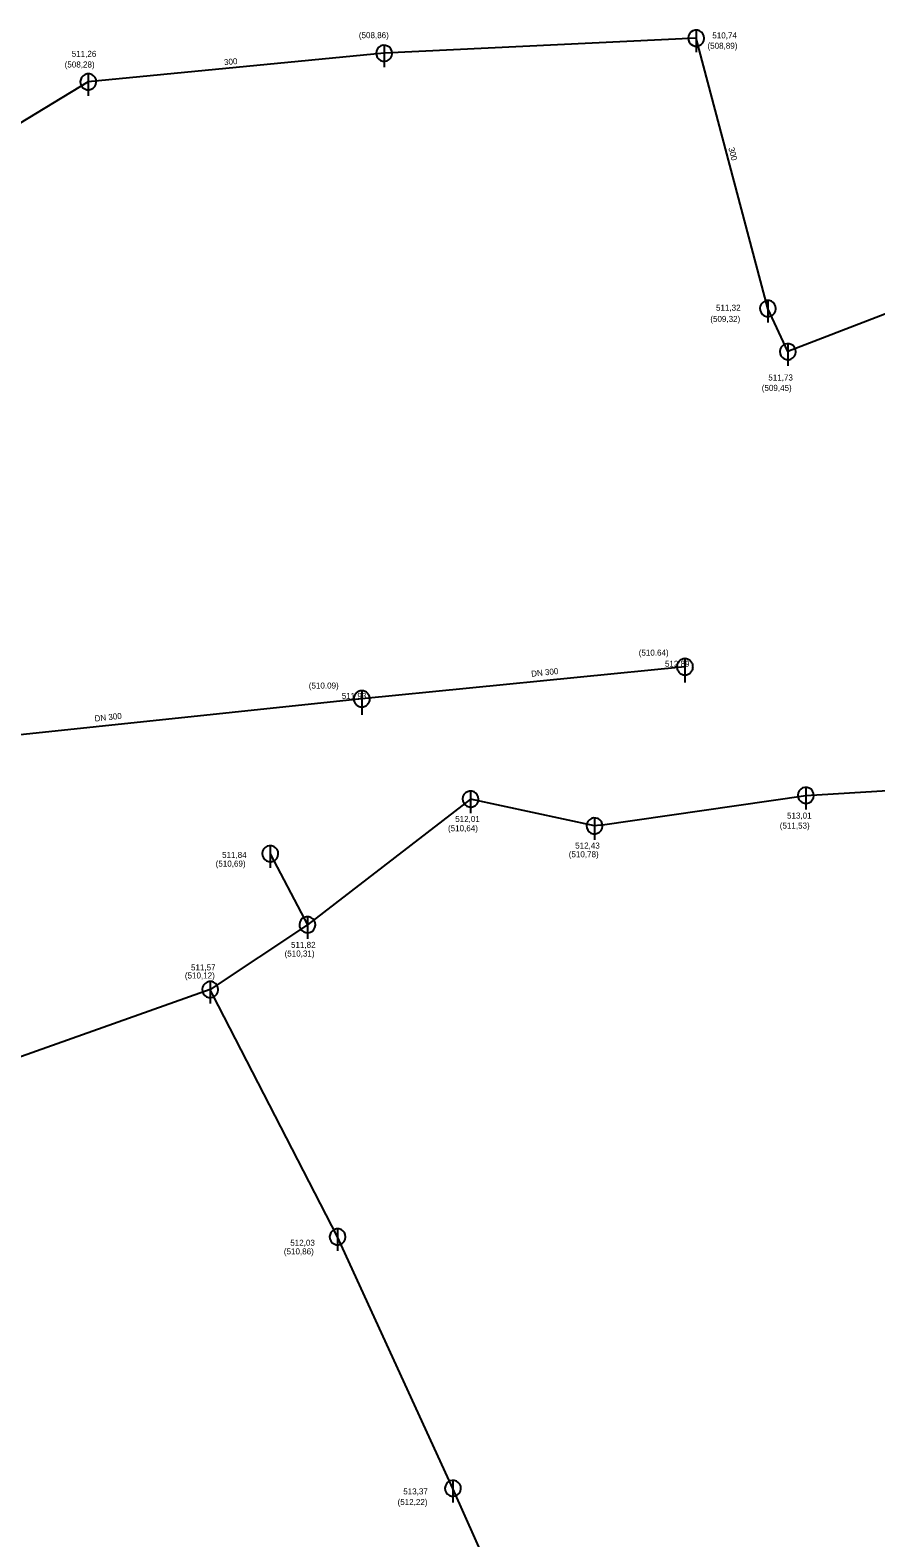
# Model space of a CAD drawing. Extents: x -476058 to -471893, y -1155786 to -1152000.
# Drawn here: x -474932.1 to -474826.6, y -1154263.3 to -1154075.2 of the extents above; entities that cross this region are included whole.
import ezdxf

# ---------------------------------------------------------------- set-up
doc = ezdxf.new("R2010")
doc.units = 0
for name, color, linetype in [('Vrstva 1', 7, 'Continuous'), ('Vrstva 10', 7, 'Continuous'), ('Vrstva 16', 7, 'Continuous'), ('Vrstva 18', 7, 'Continuous'), ('Vrstva 3', 7, 'Continuous'), ('Vrstva 35', 7, 'Continuous'), ('Vrstva 4', 7, 'Continuous'), ('Vrstva 45', 7, 'Continuous'), ('Vrstva 50', 7, 'Continuous')]:
    doc.layers.add(name, color=color, linetype=linetype)

msp = doc.modelspace()

# ---------------------------------------------------------------- linework, layer by layer
at = {"layer": 'Vrstva 1'}
for p, q in [((-474850.38, -1154154.67), (-474850.38, -1154154.67)), ((-474890.71, -1154158.68), (-474890.71, -1154158.68))]:
    msp.add_line(p, q, dxfattribs=at)
at = {"layer": 'Vrstva 10'}
for p, q in [((-474848.98, -1154075.25), (-474848.98, -1154078)), ((-474887.92, -1154077.14), (-474887.92, -1154079.88)), ((-474924.83, -1154080.7), (-474924.83, -1154083.44)), ((-474840.03, -1154108.98), (-474840.03, -1154111.73)), ((-474837.54, -1154114.36), (-474837.54, -1154117.11)), ((-474835.3, -1154169.71), (-474835.3, -1154172.46)), ((-474877.13, -1154170.17), (-474877.13, -1154172.92)), ((-474861.66, -1154173.53), (-474861.66, -1154176.27)), ((-474902.12, -1154176.99), (-474902.12, -1154179.74)), ((-474897.49, -1154185.85), (-474897.49, -1154188.6)), ((-474909.62, -1154193.94), (-474909.62, -1154196.69)), ((-474893.72, -1154224.79), (-474893.72, -1154227.54)), ((-474879.33, -1154256.17), (-474879.33, -1154258.92))]:
    msp.add_line(p, q, dxfattribs=at)
for points in [[(-474847.98, -1154076.25), (-474848.02, -1154075.97), (-474848.14, -1154075.71), (-474848.32, -1154075.5), (-474848.55, -1154075.34), (-474848.83, -1154075.26), (-474849.11, -1154075.26), (-474849.38, -1154075.33), (-474849.62, -1154075.48), (-474849.81, -1154075.69), (-474849.93, -1154075.94), (-474849.98, -1154076.22), (-474849.95, -1154076.5), (-474849.84, -1154076.76), (-474849.66, -1154076.98), (-474849.43, -1154077.14), (-474849.16, -1154077.23), (-474848.88, -1154077.25), (-474848.61, -1154077.18), (-474848.36, -1154077.04), (-474848.17, -1154076.83), (-474848.04, -1154076.58), (-474847.98, -1154076.31), (-474847.98, -1154076.25)], [(-474886.92, -1154078.14), (-474886.96, -1154077.86), (-474887.07, -1154077.6), (-474887.26, -1154077.39), (-474887.49, -1154077.23), (-474887.76, -1154077.15), (-474888.04, -1154077.14), (-474888.32, -1154077.22), (-474888.56, -1154077.37), (-474888.75, -1154077.58), (-474888.87, -1154077.83), (-474888.92, -1154078.11), (-474888.89, -1154078.39), (-474888.78, -1154078.65), (-474888.6, -1154078.87), (-474888.37, -1154079.03), (-474888.1, -1154079.12), (-474887.82, -1154079.13), (-474887.54, -1154079.06), (-474887.3, -1154078.92), (-474887.1, -1154078.72), (-474886.97, -1154078.47), (-474886.92, -1154078.19), (-474886.92, -1154078.14)], [(-474923.83, -1154081.7), (-474923.87, -1154081.42), (-474923.99, -1154081.16), (-474924.17, -1154080.94), (-474924.41, -1154080.79), (-474924.67, -1154080.71), (-474924.96, -1154080.7), (-474925.23, -1154080.78), (-474925.47, -1154080.93), (-474925.66, -1154081.14), (-474925.78, -1154081.39), (-474925.83, -1154081.67), (-474925.8, -1154081.95), (-474925.69, -1154082.21), (-474925.51, -1154082.43), (-474925.28, -1154082.59), (-474925.01, -1154082.68), (-474924.73, -1154082.69), (-474924.46, -1154082.62), (-474924.21, -1154082.48), (-474924.02, -1154082.28), (-474923.89, -1154082.03), (-474923.83, -1154081.75), (-474923.83, -1154081.7)], [(-474839.03, -1154109.98), (-474839.07, -1154109.7), (-474839.19, -1154109.44), (-474839.37, -1154109.23), (-474839.6, -1154109.07), (-474839.88, -1154108.99), (-474840.16, -1154108.99), (-474840.43, -1154109.06), (-474840.67, -1154109.21), (-474840.86, -1154109.42), (-474840.98, -1154109.67), (-474841.03, -1154109.95), (-474841, -1154110.23), (-474840.89, -1154110.49), (-474840.71, -1154110.71), (-474840.48, -1154110.87), (-474840.21, -1154110.96), (-474839.93, -1154110.98), (-474839.66, -1154110.91), (-474839.41, -1154110.77), (-474839.22, -1154110.56), (-474839.09, -1154110.31), (-474839.03, -1154110.04), (-474839.03, -1154109.98)], [(-474836.54, -1154115.36), (-474836.58, -1154115.08), (-474836.7, -1154114.82), (-474836.88, -1154114.61), (-474837.11, -1154114.46), (-474837.39, -1154114.37), (-474837.67, -1154114.37), (-474837.94, -1154114.44), (-474838.18, -1154114.59), (-474838.37, -1154114.8), (-474838.49, -1154115.05), (-474838.54, -1154115.33), (-474838.51, -1154115.61), (-474838.4, -1154115.87), (-474838.22, -1154116.09), (-474837.99, -1154116.25), (-474837.72, -1154116.34), (-474837.44, -1154116.36), (-474837.17, -1154116.29), (-474836.92, -1154116.15), (-474836.73, -1154115.94), (-474836.6, -1154115.69), (-474836.54, -1154115.42), (-474836.54, -1154115.36)], [(-474849.37, -1154154.67), (-474849.38, -1154154.56), (-474849.39, -1154154.46), (-474849.42, -1154154.36), (-474849.46, -1154154.26), (-474849.51, -1154154.17), (-474849.57, -1154154.08), (-474849.63, -1154154), (-474849.71, -1154153.92), (-474849.79, -1154153.85), (-474849.88, -1154153.8), (-474849.97, -1154153.75), (-474850.07, -1154153.71), (-474850.17, -1154153.68), (-474850.28, -1154153.67), (-474850.38, -1154153.66), (-474850.48, -1154153.67), (-474850.59, -1154153.68), (-474850.69, -1154153.71), (-474850.79, -1154153.75), (-474850.88, -1154153.8), (-474850.97, -1154153.85), (-474851.05, -1154153.92), (-474851.13, -1154154), (-474851.2, -1154154.08), (-474851.25, -1154154.17), (-474851.3, -1154154.26), (-474851.34, -1154154.36), (-474851.37, -1154154.46), (-474851.38, -1154154.56), (-474851.39, -1154154.67), (-474851.38, -1154154.78), (-474851.37, -1154154.88), (-474851.34, -1154154.98), (-474851.3, -1154155.08), (-474851.25, -1154155.17), (-474851.2, -1154155.26), (-474851.13, -1154155.34), (-474851.05, -1154155.42), (-474850.97, -1154155.49), (-474850.88, -1154155.54), (-474850.79, -1154155.59), (-474850.69, -1154155.63), (-474850.59, -1154155.66), (-474850.48, -1154155.67), (-474850.38, -1154155.68), (-474850.28, -1154155.67), (-474850.17, -1154155.66), (-474850.07, -1154155.63), (-474849.97, -1154155.59), (-474849.88, -1154155.54), (-474849.79, -1154155.49), (-474849.71, -1154155.42), (-474849.63, -1154155.34), (-474849.57, -1154155.26), (-474849.51, -1154155.17), (-474849.46, -1154155.08), (-474849.42, -1154154.98), (-474849.39, -1154154.88), (-474849.38, -1154154.78), (-474849.37, -1154154.67)], [(-474850.38, -1154153.66), (-474850.38, -1154156.64)], [(-474889.7, -1154158.68), (-474889.71, -1154158.57), (-474889.72, -1154158.47), (-474889.75, -1154158.37), (-474889.79, -1154158.27), (-474889.84, -1154158.18), (-474889.9, -1154158.09), (-474889.96, -1154158.01), (-474890.04, -1154157.93), (-474890.12, -1154157.86), (-474890.21, -1154157.81), (-474890.3, -1154157.76), (-474890.4, -1154157.72), (-474890.5, -1154157.69), (-474890.6, -1154157.68), (-474890.71, -1154157.67), (-474890.82, -1154157.68), (-474890.92, -1154157.69), (-474891.02, -1154157.72), (-474891.12, -1154157.76), (-474891.21, -1154157.81), (-474891.3, -1154157.86), (-474891.39, -1154157.93), (-474891.46, -1154158.01), (-474891.53, -1154158.09), (-474891.58, -1154158.18), (-474891.63, -1154158.27), (-474891.67, -1154158.37), (-474891.7, -1154158.47), (-474891.71, -1154158.57), (-474891.72, -1154158.68), (-474891.71, -1154158.78), (-474891.7, -1154158.89), (-474891.67, -1154158.99), (-474891.63, -1154159.09), (-474891.58, -1154159.18), (-474891.53, -1154159.27), (-474891.46, -1154159.35), (-474891.39, -1154159.43), (-474891.3, -1154159.5), (-474891.21, -1154159.55), (-474891.12, -1154159.6), (-474891.02, -1154159.64), (-474890.92, -1154159.67), (-474890.82, -1154159.68), (-474890.71, -1154159.69), (-474890.6, -1154159.68), (-474890.5, -1154159.67), (-474890.4, -1154159.64), (-474890.3, -1154159.6), (-474890.21, -1154159.55), (-474890.12, -1154159.5), (-474890.04, -1154159.43), (-474889.96, -1154159.35), (-474889.9, -1154159.27), (-474889.84, -1154159.18), (-474889.79, -1154159.09), (-474889.75, -1154158.99), (-474889.72, -1154158.89), (-474889.71, -1154158.78), (-474889.7, -1154158.68)], [(-474890.71, -1154157.67), (-474890.71, -1154160.65)], [(-474834.3, -1154170.71), (-474834.34, -1154170.43), (-474834.46, -1154170.17), (-474834.64, -1154169.96), (-474834.88, -1154169.8), (-474835.15, -1154169.72), (-474835.43, -1154169.72), (-474835.7, -1154169.79), (-474835.94, -1154169.94), (-474836.13, -1154170.15), (-474836.25, -1154170.4), (-474836.3, -1154170.68), (-474836.27, -1154170.96), (-474836.16, -1154171.22), (-474835.98, -1154171.44), (-474835.75, -1154171.6), (-474835.48, -1154171.69), (-474835.2, -1154171.71), (-474834.93, -1154171.64), (-474834.68, -1154171.5), (-474834.49, -1154171.29), (-474834.36, -1154171.04), (-474834.3, -1154170.77), (-474834.3, -1154170.71)], [(-474876.13, -1154171.17), (-474876.17, -1154170.89), (-474876.29, -1154170.64), (-474876.47, -1154170.42), (-474876.7, -1154170.27), (-474876.97, -1154170.18), (-474877.26, -1154170.18), (-474877.53, -1154170.26), (-474877.77, -1154170.4), (-474877.96, -1154170.61), (-474878.08, -1154170.87), (-474878.13, -1154171.14), (-474878.1, -1154171.43), (-474877.99, -1154171.69), (-474877.81, -1154171.9), (-474877.58, -1154172.07), (-474877.31, -1154172.16), (-474877.03, -1154172.17), (-474876.76, -1154172.1), (-474876.51, -1154171.96), (-474876.32, -1154171.76), (-474876.19, -1154171.51), (-474876.13, -1154171.23), (-474876.13, -1154171.17)], [(-474860.66, -1154174.53), (-474860.7, -1154174.25), (-474860.81, -1154173.99), (-474861, -1154173.78), (-474861.23, -1154173.62), (-474861.5, -1154173.54), (-474861.79, -1154173.53), (-474862.06, -1154173.61), (-474862.3, -1154173.76), (-474862.49, -1154173.97), (-474862.61, -1154174.22), (-474862.66, -1154174.5), (-474862.63, -1154174.78), (-474862.52, -1154175.04), (-474862.34, -1154175.26), (-474862.11, -1154175.42), (-474861.84, -1154175.51), (-474861.56, -1154175.52), (-474861.28, -1154175.45), (-474861.04, -1154175.31), (-474860.85, -1154175.11), (-474860.72, -1154174.86), (-474860.66, -1154174.58), (-474860.66, -1154174.53)], [(-474901.12, -1154177.99), (-474901.16, -1154177.71), (-474901.28, -1154177.46), (-474901.46, -1154177.24), (-474901.7, -1154177.09), (-474901.97, -1154177), (-474902.25, -1154177), (-474902.52, -1154177.07), (-474902.76, -1154177.22), (-474902.95, -1154177.43), (-474903.08, -1154177.69), (-474903.12, -1154177.96), (-474903.09, -1154178.25), (-474902.98, -1154178.51), (-474902.81, -1154178.72), (-474902.58, -1154178.89), (-474902.31, -1154178.98), (-474902.03, -1154178.99), (-474901.75, -1154178.92), (-474901.51, -1154178.78), (-474901.31, -1154178.57), (-474901.18, -1154178.32), (-474901.13, -1154178.05), (-474901.12, -1154177.99)], [(-474896.49, -1154186.85), (-474896.53, -1154186.57), (-474896.65, -1154186.31), (-474896.83, -1154186.1), (-474897.06, -1154185.95), (-474897.33, -1154185.86), (-474897.62, -1154185.86), (-474897.89, -1154185.93), (-474898.13, -1154186.08), (-474898.32, -1154186.29), (-474898.44, -1154186.54), (-474898.49, -1154186.82), (-474898.46, -1154187.1), (-474898.35, -1154187.36), (-474898.17, -1154187.58), (-474897.94, -1154187.75), (-474897.67, -1154187.83), (-474897.39, -1154187.85), (-474897.11, -1154187.78), (-474896.87, -1154187.64), (-474896.68, -1154187.43), (-474896.55, -1154187.18), (-474896.49, -1154186.91), (-474896.49, -1154186.85)], [(-474908.62, -1154194.94), (-474908.66, -1154194.66), (-474908.78, -1154194.4), (-474908.96, -1154194.19), (-474909.2, -1154194.03), (-474909.47, -1154193.95), (-474909.75, -1154193.95), (-474910.02, -1154194.02), (-474910.26, -1154194.17), (-474910.45, -1154194.38), (-474910.57, -1154194.63), (-474910.62, -1154194.91), (-474910.59, -1154195.19), (-474910.48, -1154195.45), (-474910.3, -1154195.67), (-474910.07, -1154195.83), (-474909.8, -1154195.92), (-474909.52, -1154195.94), (-474909.25, -1154195.87), (-474909, -1154195.73), (-474908.81, -1154195.52), (-474908.68, -1154195.27), (-474908.62, -1154195), (-474908.62, -1154194.94)], [(-474892.72, -1154225.79), (-474892.76, -1154225.51), (-474892.88, -1154225.25), (-474893.06, -1154225.04), (-474893.3, -1154224.89), (-474893.57, -1154224.8), (-474893.85, -1154224.8), (-474894.12, -1154224.87), (-474894.36, -1154225.02), (-474894.55, -1154225.23), (-474894.67, -1154225.48), (-474894.72, -1154225.76), (-474894.69, -1154226.04), (-474894.58, -1154226.3), (-474894.4, -1154226.52), (-474894.17, -1154226.68), (-474893.91, -1154226.77), (-474893.62, -1154226.79), (-474893.35, -1154226.72), (-474893.1, -1154226.58), (-474892.91, -1154226.37), (-474892.78, -1154226.12), (-474892.72, -1154225.85), (-474892.72, -1154225.79)], [(-474878.33, -1154257.17), (-474878.36, -1154256.89), (-474878.48, -1154256.63), (-474878.66, -1154256.42), (-474878.9, -1154256.26), (-474879.17, -1154256.18), (-474879.45, -1154256.18), (-474879.72, -1154256.25), (-474879.96, -1154256.4), (-474880.15, -1154256.61), (-474880.28, -1154256.86), (-474880.33, -1154257.14), (-474880.29, -1154257.42), (-474880.18, -1154257.68), (-474880.01, -1154257.9), (-474879.78, -1154258.06), (-474879.51, -1154258.15), (-474879.23, -1154258.16), (-474878.95, -1154258.09), (-474878.71, -1154257.95), (-474878.51, -1154257.75), (-474878.38, -1154257.5), (-474878.33, -1154257.22), (-474878.33, -1154257.17)]]:
    msp.add_lwpolyline(points, dxfattribs=at)
at = {"layer": 'Vrstva 35'}
msp.add_lwpolyline([(-474850.38, -1154154.67), (-474890.71, -1154158.68), (-474940.09, -1154163.87), (-474990.69, -1154169.83), (-475017.24, -1154174.14), (-475043.32, -1154186.7), (-475043.59, -1154187.73)], dxfattribs=at)
at = {"layer": 'Vrstva 45'}
for points in [[(-474848.98, -1154076.25), (-474887.92, -1154078.14)], [(-474840.03, -1154109.98), (-474848.98, -1154076.25)], [(-474887.92, -1154078.14), (-474924.83, -1154081.7)], [(-474924.83, -1154081.7), (-474969.11, -1154108.55)], [(-474780.82, -1154093.49), (-474837.54, -1154115.36)], [(-474837.54, -1154115.36), (-474840.03, -1154109.98)], [(-474877.13, -1154171.17), (-474897.49, -1154186.85)], [(-474861.66, -1154174.53), (-474877.13, -1154171.17)], [(-474897.49, -1154186.85), (-474909.62, -1154194.94)], [(-474909.62, -1154194.94), (-474938.95, -1154205.34)]]:
    msp.add_lwpolyline(points, dxfattribs=at)
at = {"layer": 'Vrstva 50'}
for points in [[(-474835.3, -1154170.71), (-474815.55, -1154169.54)], [(-474860.97, -1154174.43), (-474835.3, -1154170.71)], [(-474860.97, -1154174.43), (-474861.66, -1154174.53)], [(-474902.12, -1154177.99), (-474897.85, -1154186.16), (-474897.49, -1154186.85)], [(-474909.29, -1154195.58), (-474909.62, -1154194.94)], [(-474893.72, -1154225.79), (-474909.29, -1154195.58)], [(-474879.33, -1154257.17), (-474893.72, -1154225.79)], [(-474858.62, -1154303.63), (-474879.33, -1154257.17)]]:
    msp.add_lwpolyline(points, dxfattribs=at)

# ---------------------------------------------------------------- texts
at = {"layer": 'Vrstva 16'}
for p in [(-474869.53, -1154155.92), (-474924.01, -1154161.51)]:
    msp.add_text('DN 300', height=0.75, rotation=6.0006, dxfattribs=at).set_placement(p)
at = {"layer": 'Vrstva 18'}
for rotation, p in [(5.5072, (-474907.86, -1154079.63)), (284.8606, (-474844.97, -1154089.97))]:
    msp.add_text('300 ', height=0.75, rotation=rotation, dxfattribs=at).set_placement(p)
at = {"layer": 'Vrstva 3'}
for s, p in [('510,74', (-474846.97, -1154076.28)), ('511,26', (-474926.9, -1154078.58)), ('511,32', (-474846.51, -1154110.25)), ('511,73', (-474839.98, -1154118.96)), ('512 89 ', (-474852.88, -1154154.67)), ('511 93 ', (-474893.21, -1154158.68)), ('512,01', (-474879.05, -1154174.03)), ('513,01', (-474837.65, -1154173.61)), ('512,43', (-474864.08, -1154177.35)), ('511,84', (-474908.14, -1154178.52)), ('511,82', (-474899.54, -1154189.74)), ('511,57', (-474912.02, -1154192.55)), ('512,03', (-474899.63, -1154226.9)), ('513,37', (-474885.53, -1154257.92))]:
    msp.add_text(s, height=0.75, dxfattribs=at).set_placement(p)
at = {"layer": 'Vrstva 4'}
for s, p in [('(508,86)', (-474891.07, -1154076.25)), ('(508,89)', (-474847.57, -1154077.57)), ('(508,28)', (-474927.78, -1154079.91)), ('(509,32)', (-474847.22, -1154111.65)), ('(509,45)', (-474840.8, -1154120.25)), ('(510.64) ', (-474856.15, -1154153.28)), ('(510.09) ', (-474897.32, -1154157.39)), ('(510,64)', (-474879.95, -1154175.19)), ('(511,53)', (-474838.55, -1154174.86)), ('(510,69)', (-474908.94, -1154179.6)), ('(510,78)', (-474864.88, -1154178.43)), ('(510,31)', (-474900.34, -1154190.82)), ('(510,12)', (-474912.78, -1154193.56)), ('(510,86)', (-474900.43, -1154227.98)), ('(512,22)', (-474886.24, -1154259.25))]:
    msp.add_text(s, height=0.75, dxfattribs=at).set_placement(p)

doc.saveas('drawing.dxf')
